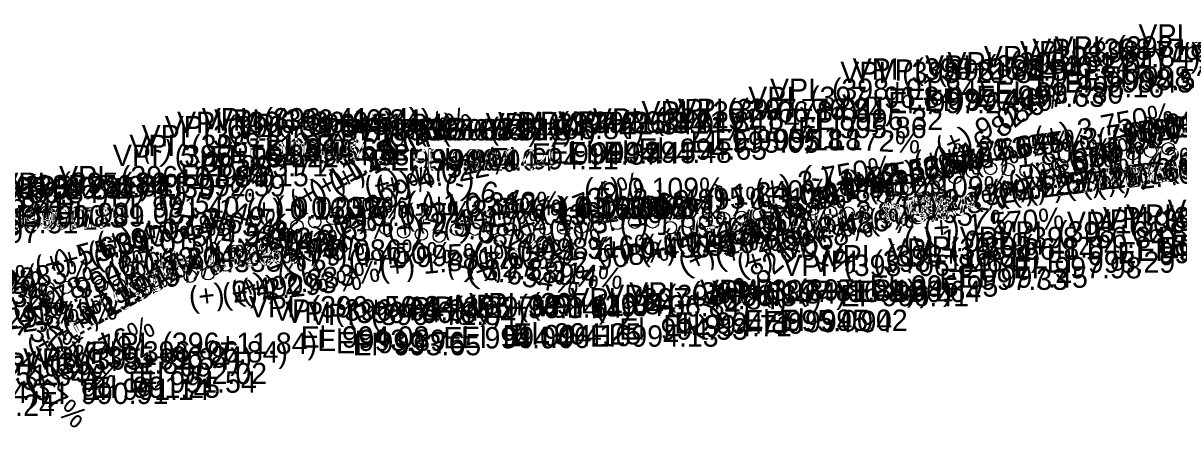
# Model space of a CAD drawing. Extents: x 16970812 to 16976737, y 12558429 to 12559451.
# Drawn here: x 16973947.7 to 16974272.7, y 12558853.6 to 12558967.5 of the extents above; entities that cross this region are included whole.
import ezdxf

# ---------------------------------------------------------------- set-up
doc = ezdxf.new("R2010")
doc.units = 0
doc.layers.add('RD_DDB_GradeTX', color=7, linetype='Continuous')
doc.layers.add('RD_DDB_PI', color=7, linetype='Continuous')

msp = doc.modelspace()

# ---------------------------------------------------------------- linework, layer by layer
at = {"layer": 'RD_DDB_PI'}
for centre in [(16974264.74, 12558931.47), (16974269.74, 12558932.13), (16974244.74, 12558928.33), (16974249.74, 12558929.2), (16974254.74, 12558930.1), (16974259.74, 12558930.78), (16974214.74, 12558925.66), (16974219.74, 12558926.59), (16974224.74, 12558926.3), (16974229.74, 12558925.95), (16974234.74, 12558926.55), (16974239.74, 12558927.44), (16974199.74, 12558921.35), (16974204.74, 12558922.52), (16974209.74, 12558924.04), (16974189.74, 12558918.63), (16974194.74, 12558920.9), (16974164.74, 12558915.19), (16974169.74, 12558915.22), (16974029.74, 12558911.58), (16974034.74, 12558912.59), (16974039.74, 12558912.25), (16974119.74, 12558911.49), (16974124.74, 12558911.57), (16974134.74, 12558911.69), (16974139.74, 12558911.94), (16974144.74, 12558912.55), (16974149.74, 12558912.88), (16974154.74, 12558913.61), (16974159.74, 12558914.54), (16974174.74, 12558914.3), (16974179.74, 12558914.03), (16974184.74, 12558914.42), (16974024.74, 12558910.39), (16974044.74, 12558910.98), (16974049.74, 12558909.7), (16974054.74, 12558908.78), (16974069.74, 12558909.49), (16974074.74, 12558909.53), (16974079.74, 12558909.53), (16974084.74, 12558909.51), (16974089.74, 12558909.49), (16974094.74, 12558909.6), (16974099.74, 12558909.86), (16974104.74, 12558910.11), (16974109.74, 12558910.58), (16974114.74, 12558911.18), (16974129.74, 12558909.97), (16974014.74, 12558905.08), (16974019.74, 12558907.85), (16974059.74, 12558908.14), (16974064.74, 12558907.56), (16974009.74, 12558902.26), (16974004.74, 12558899.44), (16973989.74, 12558895.58), (16973994.74, 12558896.3), (16973999.74, 12558897.02), (16973954.74, 12558892.88), (16973959.74, 12558893.18), (16973964.74, 12558893.48), (16973969.74, 12558893.76), (16973974.74, 12558893.85), (16973979.74, 12558894.47), (16973984.74, 12558895.01), (16973949.74, 12558891.86)]:
    msp.add_circle(centre, 1.75, dxfattribs=at)

# ---------------------------------------------------------------- texts
at = {"layer": 'RD_DDB_GradeTX'}
for s, rotation, p in [('(+) 16.821%', 40.0653, (16974205.12, 12558919.8)), ('(+) 9.086%', 24.4333, (16974206.01, 12558929.31)), ('(+) 3.526%', 9.9989, (16974257.4, 12558933.61)), ('(+) 3.508%', 9.9478, (16974262.53, 12558934.49)), ('(+) 2.766%', 7.8748, (16974269.24, 12558935.21)), ('(+) 11.072%', 28.9696, (16974030.11, 12558917.02)), ('(+) 10.173%', 26.9604, (16974035.47, 12558919.22)), ('(+) 3.750%', 10.6204, (16974232.74, 12558932.08)), ('(+) 3.015%', 8.5738, (16974250.25, 12558931.66)), ('(+) 2.996%', 8.5208, (16974254.14, 12558932.3)), ('(+) 2.942%', 8.3668, (16974258.77, 12558933.16)), ('(+) 2.854%', 8.1227, (16974263.74, 12558934.16)), ('(+) 11.289%', 29.4431, (16974024.86, 12558914.24)), ('(+) 2.795%', 7.9563, (16974234.02, 12558930.02)), ('(-) 1.172%', 356.6475, (16974162.39, 12558932.96)), ('(+) 2.753%', 7.8386, (16974198.59, 12558925.39)), ('(+) 2.665%', 7.5888, (16974203.8, 12558926.38)), ('(+) 2.645%', 7.5339, (16974208.8, 12558927.1)), ('(+) 6.068%', 16.8769, (16974225.76, 12558919.49)), ('(+) 6.467%', 17.9175, (16974231.2, 12558921.52)), ('(+) 3.576%', 10.1379, (16974270.02, 12558923.69)), ('(-) 5.082%', 345.742, (16973981.17, 12558930.23)), ('(+) 4.751%', 13.3624, (16974044.43, 12558918.15)), ('(+) 3.576%', 10.1379, (16974189.24, 12558921.43)), ('(+) 1.806%', 5.1588, (16974215.16, 12558925.75)), ('(-) 1.172%', 356.6475, (16974242.24, 12558928.28)), ('(-) 1.421%', 355.9359, (16974247.08, 12558927.72)), ('(+) 3.589%', 10.1734, (16974254.74, 12558920.99)), ('(+) 4.022%', 11.3718, (16974047.43, 12558918.2)), ('(+) 3.750%', 10.6204, (16974154.2, 12558917.36)), ('(+) 3.589%', 10.1734, (16974173.95, 12558918.69)), ('(+) 2.606%', 7.423, (16974178.19, 12558919.97)), ('(+) 3.526%', 9.9989, (16974178.7, 12558919.73)), ('(+) 4.694%', 13.2093, (16974220.75, 12558917.04)), ('(+) 2.776%', 7.9034, (16974241.07, 12558918.95)), ('(+) 2.889%', 8.2204, (16974245.59, 12558919.23)), ('(+) 2.408%', 6.8641, (16974249.56, 12558919.27)), ('(+) 11.299%', 29.4638, (16974025.86, 12558901.03)), ('(-) 6.401%', 342.2536, (16974065.93, 12558920.94)), ('(+) 6.914%', 19.069, (16974152.53, 12558908.32)), ('(-) 1.421%', 355.9359, (16974166.45, 12558921.42)), ('(+) 2.625%', 7.4787, (16974215, 12558915.88)), ('(+) 2.671%', 7.6059, (16974222.32, 12558916.71)), ('(+) 2.704%', 7.6996, (16974225.71, 12558917.06)), ('(+) 2.728%', 7.7659, (16974230.38, 12558917.62)), ('(-) 1.337%', 356.1754, (16973975.44, 12558919.56)), ('(+) 7.739%', 21.1528, (16974086.09, 12558906.17)), ('(+) 0.109%', 0.3115, (16974105.49, 12558917.87)), ('(-) 3.657%', 349.6382, (16974108.2, 12558917.32)), ('(+) 1.240%', 3.549, (16974135.05, 12558915.44)), ('(+) 6.467%', 17.9175, (16974151.63, 12558908.4)), ('(+) 0.998%', 2.857, (16974153.8, 12558915.65)), ('(+) 1.316%', 3.766, (16974166.62, 12558917)), ('(+) 0.109%', 0.3115, (16974185.49, 12558918.3)), ('(+) 2.732%', 7.779, (16974195.09, 12558912.87)), ('(-) 5.149%', 345.5629, (16973985.29, 12558916.99)), ('(-) 1.337%', 356.1754, (16974055.25, 12558914.22)), ('(+) 0.313%', 0.8955, (16974059.76, 12558913.55)), ('(+) 2.606%', 7.423, (16974098.9, 12558909.64)), ('(+) 0.995%', 2.8486, (16974118.68, 12558913.81)), ('(+) 0.313%', 0.8955, (16974139.75, 12558914.8)), ('(+) 2.408%', 6.8641, (16974170.17, 12558909.71)), ('(+) 3.716%', 10.5244, (16974176.8, 12558908.55)), ('(+) 3.508%', 9.9478, (16974185.88, 12558908.87)), ('(-) 3.657%', 349.6382, (16974188.97, 12558914.75)), ('(-) 3.654%', 349.6474, (16973988.02, 12558911.82)), ('(+) 0.160%', 0.4597, (16974010.49, 12558912.02)), ('(-) 0.023%', 359.9331, (16974013.21, 12558912.6)), ('(-) 0.055%', 359.8434, (16974018.51, 12558912.69)), ('(+) 9.676%', 25.818, (16974021.35, 12558897.47)), ('(+) 1.023%', 2.9289, (16974034.79, 12558909.54)), ('(+) 2.401%', 6.8459, (16974050.37, 12558906.47)), ('(+) 1.240%', 3.549, (16974055.21, 12558910.49)), ('(+) 2.436%', 6.945, (16974078.57, 12558907.51)), ('(+) 0.160%', 0.4597, (16974090.48, 12558912.66)), ('(-) 0.023%', 359.9331, (16974093.21, 12558912.51)), ('(+) 3.716%', 10.5244, (16974096.04, 12558905.76)), ('(-) 0.055%', 359.8434, (16974098.51, 12558912.47)), ('(-) 0.086%', 359.7535, (16974103.87, 12558912.43)), ('(+) 9.086%', 24.4333, (16974133.62, 12558896.43)), ('(+) 2.908%', 8.2731, (16974169.72, 12558906.69)), ('(+) 4.751%', 13.3624, (16973966.73, 12558899.7)), ('(+) 4.022%', 11.3718, (16973969.09, 12558902.44)), ('(-) 2.589%', 352.6251, (16973992.89, 12558907.71)), ('(+) 2.873%', 8.1736, (16974012.88, 12558901.94)), ('(-) 5.082%', 345.742, (16974058.55, 12558910.57)), ('(-) 5.149%', 345.5629, (16974065.6, 12558908.71)), ('(-) 1.097%', 356.8612, (16974115.41, 12558908.54)), ('(+) 2.401%', 6.8459, (16974131.2, 12558904.09)), ('(+) 1.806%', 5.1588, (16974136.58, 12558906.61)), ('(+) 4.694%', 13.2093, (16974143, 12558898.79)), ('(-) 6.401%', 342.2536, (16974145.55, 12558908.06)), ('(+) 2.436%', 6.945, (16974159.39, 12558905.27)), ('(+) 1.570%', 4.4896, (16974201.21, 12558906.69)), ('(+) 5.636%', 15.7391, (16973952.04, 12558895.75)), ('(+) 5.390%', 15.0828, (16973957.02, 12558896.93)), ('(+) 4.078%', 11.524, (16973968.16, 12558898.68)), ('(-) 2.314%', 353.401, (16973999.37, 12558906.06)), ('(+) 6.914%', 19.069, (16974073.28, 12558893.62)), ('(+) 1.881%', 5.372, (16974127.79, 12558903.24)), ('(+) 16.821%', 40.0653, (16974137.34, 12558878.48)), ('(+) 6.068%', 16.8769, (16974149.42, 12558896.33)), ('(-) 1.097%', 356.8612, (16974195.28, 12558904.16)), ('(+) 10.173%', 26.9604, (16973964.71, 12558883.22)), ('(+) 2.141%', 6.1104, (16974001.48, 12558899.81)), ('(+) 7.739%', 21.1528, (16974007.49, 12558888.62)), ('(-) 0.086%', 359.7535, (16974023.82, 12558900.77)), ('(+) 0.998%', 2.857, (16974074.5, 12558899.68)), ('(+) 1.316%', 3.766, (16974087.59, 12558899.77)), ('(+) 0.450%', 1.2892, (16974108.94, 12558900.92)), ('(+) 1.023%', 2.9289, (16974115.29, 12558901.64)), ('(+) 1.570%', 4.4896, (16974121.47, 12558900.43)), ('(+) 8.543%', 23.129, (16973950.47, 12558884.69)), ('(+) 11.072%', 28.9696, (16973960.75, 12558878.62)), ('(+) 1.204%', 3.4464, (16973975.06, 12558897.11)), ('(+) 1.192%', 3.4094, (16973981.71, 12558897.5)), ('(+) 1.123%', 3.2124, (16973986.31, 12558897.7)), ('(+) 0.338%', 0.9695, (16973988.09, 12558897.07)), ('(+) 0.450%', 1.2892, (16974028.96, 12558899.12)), ('(+) 0.995%', 2.8486, (16974039.38, 12558897.84)), ('(+) 1.881%', 5.372, (16974048.16, 12558895.75)), ('(-) 2.589%', 352.6251, (16974072.19, 12558897.45)), ('(+) 2.908%', 8.2731, (16974090.6, 12558895.19)), ('(-) 1.481%', 355.7651, (16973912.32, 12558894.42)), ('(+) 2.883%', 8.2022, (16973928.46, 12558889.78)), ('(+) 7.990%', 21.7763, (16973946.21, 12558882.51)), ('(+) 11.289%', 29.4431, (16973955.84, 12558875.28)), ('(+) 5.397%', 15.102, (16973965.43, 12558886.77)), ('(+) 2.883%', 8.2022, (16974009.3, 12558889.3)), ('(-) 3.654%', 349.6474, (16974066.64, 12558897.46)), ('(-) 2.314%', 353.401, (16974078.81, 12558896.87)), ('(+) 2.490%', 7.0961, (16973913.87, 12558889.29)), ('(-) 1.721%', 355.0806, (16973917.28, 12558893.79)), ('(-) 2.923%', 351.6863, (16973918.33, 12558892.6)), ('(-) 3.336%', 350.53, (16973923.21, 12558891.51)), ('(+) 11.299%', 29.4638, (16973950.95, 12558872.49)), ('(+) 2.490%', 7.0961, (16973994.7, 12558887.26)), ('(+) 2.293%', 6.5394, (16974003.99, 12558888.15)), ('(-) 7.737%', 338.8521, (16973929.09, 12558886.45)), ('(+) 2.141%', 6.1104, (16973923.24, 12558879.37)), ('(+) 2.293%', 6.5394, (16973924.55, 12558879.05)), ('(+) 2.873%', 8.1736, (16973935.45, 12558878.69)), ('(+) 9.676%', 25.818, (16973949.83, 12558862.87)), ('(-) 16.557%', 320.3797, (16973930.29, 12558879.81)), ('(-) 4.089%', 348.4452, (16973936.78, 12558871.98))]:
    msp.add_text(s, height=6, rotation=rotation, dxfattribs=at).set_placement(p)
at = {"layer": 'RD_DDB_PI'}
for s, p in [('VPI  (399+06.84)', (16974261.33, 12558961.18)), ('VPI  (398+71.84)', (16974228.04, 12558956.47)), ('VPI  (398+76.84)', (16974231.5, 12558957.13)), ('VPI  (398+81.84)', (16974237.74, 12558957.8)), ('VPI  (398+46.84)', (16974201.33, 12558952.44)), ('VPI  (398+51.84)', (16974207.63, 12558953.33)), ('VPI  (398+61.84)', (16974217.86, 12558955.1)), ('VPI  (398+21.84)', (16974177.51, 12558950.66)), ('VPI  (398+26.84)', (16974180.97, 12558951.59)), ('VPI  (398+31.84)', (16974187.45, 12558951.3)), ('El  998.70', (16974250.94, 12558949.3)), ('VPI  (398+01.84)', (16974157.74, 12558945.9)), ('El  998.16', (16974232.42, 12558946.6)), ('El  998.43', (16974240.5, 12558947.97)), ('El  998.56', (16974245.65, 12558948.63)), ('VPI  (397+96.84)', (16974151.62, 12558943.63)), ('El  997.46', (16974196.18, 12558943.09)), ('El  997.40', (16974201.06, 12558942.8)), ('El  997.63', (16974215.79, 12558943.94)), ('El  997.80', (16974220.94, 12558944.83)), ('VPI  (397+66.84)', (16974121.62, 12558939.54)), ('VPI  (397+71.84)', (16974128.33, 12558940.19)), ('VPI  (397+76.84)', (16974131.8, 12558940.22)), ('El  997.27', (16974191, 12558942.16)), ('VPI  (396+36.84)', (16973991.03, 12558936.58)), ('VPI  (396+41.84)', (16973997.98, 12558937.59)), ('VPI  (396+46.84)', (16974001.44, 12558937.25)), ('VPI  (397+21.84)', (16974077.8, 12558936.18)), ('VPI  (397+26.84)', (16974081.27, 12558936.49)), ('VPI  (397+31.84)', (16974087.74, 12558936.57)), ('VPI  (397+41.84)', (16974098.16, 12558936.69)), ('VPI  (397+51.84)', (16974107.92, 12558937.55)), ('El  996.32', (16974170.26, 12558937.4)), ('VPI  (396+31.84)', (16973987.57, 12558935.39)), ('VPI  (396+51.84)', (16974007.74, 12558935.98)), ('VPI  (396+76.84)', (16974031.62, 12558934.49)), ('VPI  (396+81.84)', (16974037.86, 12558934.53)), ('VPI  (396+86.84)', (16974041.33, 12558934.53)), ('VPI  (396+91.84)', (16974047.98, 12558934.51)), ('VPI  (397+06.84)', (16974061.5, 12558934.86)), ('El  995.86', (16974165.65, 12558935.13)), ('VPI  (396+21.84)', (16973977.63, 12558930.08)), ('VPI  (396+26.84)', (16973981.09, 12558932.85)), ('El  995.05', (16974135.44, 12558931.04)), ('El  995.18', (16974142.21, 12558931.69)), ('El  995.18', (16974147.21, 12558931.72)), ('VPI  (396+16.84)', (16973972.98, 12558927.26)), ('El  994.22', (16974000.32, 12558926.89)), ('El  994.45', (16974005.79, 12558928.08)), ('El  994.66', (16974011, 12558929.09)), ('El  994.59', (16974015.76, 12558928.75)), ('El  994.33', (16974020.2, 12558927.48)), ('El  994.37', (16974090.76, 12558927.68)), ('El  994.44', (16974096, 12558927.99)), ('El  994.45', (16974100.79, 12558928.07)), ('El  994.48', (16974110.91, 12558928.19)), ('El  994.65', (16974120.79, 12558929.05)), ('El  993.71', (16973997.3, 12558924.35)), ('El  994.04', (16974045.88, 12558925.99)), ('El  994.04', (16974050.88, 12558926.03)), ('El  994.04', (16974055.88, 12558926.03)), ('El  994.04', (16974060.88, 12558926.01)), ('El  994.11', (16974079.07, 12558926.36)), ('VPI  (396+01.84)', (16973957.86, 12558921.3)), ('El  993.15', (16973991.92, 12558921.58)), ('VPI  (395+56.84)', (16973910.97, 12558916.86)), ('VPI  (395+61.84)', (16973917.74, 12558917.88)), ('VPI  (395+66.84)', (16973921.21, 12558918.18)), ('VPI  (395+71.84)', (16973927.92, 12558918.48)), ('VPI  (395+76.84)', (16973931.39, 12558918.76)), ('VPI  (395+86.84)', (16973941.09, 12558919.47)), ('El  992.59', (16973985.41, 12558918.76)), ('VPI  (395+46.84)', (16973901.21, 12558914.17)), ('VPI  (395+41.84)', (16973897.74, 12558912.76)), ('El  990.89', (16973945.76, 12558910.26)), ('El  991.03', (16973957.03, 12558910.97)), ('El  991.40', (16973972.42, 12558912.8)), ('VPI  (399+01.84)', (16974257.86, 12558910.48)), ('VPI  (399+11.84)', (16974269.51, 12558911.87)), ('El  990.51', (16973927.18, 12558908.36)), ('El  990.71', (16973932.6, 12558909.38)), ('El  990.77', (16973936.24, 12558909.68)), ('El  990.83', (16973940.38, 12558909.98)), ('VPI  (398+86.84)', (16974241.21, 12558908.45)), ('VPI  (398+91.84)', (16974247.86, 12558909.12)), ('VPI  (398+96.84)', (16974251.33, 12558909.8)), ('El  989.97', (16973916.06, 12558905.67)), ('VPI  (398+56.84)', (16974211.09, 12558904.2)), ('VPI  (398+66.84)', (16974221.33, 12558905.78)), ('VPI  (398+36.84)', (16974190.91, 12558900.95)), ('VPI  (398+41.84)', (16974197.86, 12558901.55)), ('El  998.96', (16974260.88, 12558900.62)), ('El  999.10', (16974267.42, 12558901.3)), ('El  999.23', (16974270.26, 12558901.98)), ('VPI  (398+11.84)', (16974169.4, 12558897.52)), ('VPI  (398+16.84)', (16974172.86, 12558899.04)), ('El  998.29', (16974235.53, 12558897.28)), ('El  998.83', (16974255.38, 12558899.95)), ('VPI  (398+06.84)', (16974161.21, 12558896.35)), ('El  997.98', (16974226.09, 12558895.7)), ('El  997.33', (16974205.38, 12558892.45)), ('El  997.45', (16974210.97, 12558893.05)), ('VPI  (397+56.84)', (16974111.39, 12558887.88)), ('VPI  (397+61.84)', (16974118.16, 12558888.61)), ('VPI  (397+81.84)', (16974138.04, 12558889.3)), ('VPI  (397+86.84)', (16974141.5, 12558889.03)), ('VPI  (397+91.84)', (16974148.16, 12558889.42)), ('El  996.41', (16974177.54, 12558887.85)), ('El  996.64', (16974181, 12558889.02)), ('El  996.95', (16974185.79, 12558890.54)), ('VPI  (396+56.84)', (16974011.21, 12558884.7)), ('VPI  (396+96.84)', (16974051.44, 12558884.49)), ('VPI  (397+01.84)', (16974058.04, 12558884.6)), ('VPI  (397+11.84)', (16974069.69, 12558885.11)), ('VPI  (397+16.84)', (16974073.16, 12558885.58)), ('VPI  (397+36.84)', (16974091.21, 12558884.97)), ('VPI  (397+46.84)', (16974101.62, 12558886.94)), ('VPI  (396+61.84)', (16974017.98, 12558883.78)), ('VPI  (396+66.84)', (16974021.44, 12558883.14)), ('VPI  (396+71.84)', (16974028.16, 12558882.56)), ('El  995.02', (16974160.32, 12558880.92)), ('El  994.53', (16974115.38, 12558878.44)), ('El  994.71', (16974127.71, 12558879.38)), ('El  994.86', (16974130.88, 12558880.11)), ('El  995.00', (16974150.53, 12558880.8)), ('El  994.94', (16974156, 12558880.53)), ('VPI  (396+11.84)', (16973969.51, 12558874.44)), ('El  994.08', (16974025.79, 12558876.2)), ('El  993.89', (16974030.47, 12558875.28)), ('El  993.76', (16974035.76, 12558874.64)), ('El  994.04', (16974065.88, 12558875.99)), ('El  994.06', (16974070.88, 12558876.1)), ('El  994.16', (16974082.54, 12558876.61)), ('El  994.25', (16974085.44, 12558877.08)), ('El  994.13', (16974107.15, 12558876.47)), ('VPI  (396+06.84)', (16973961.33, 12558872.02)), ('El  993.65', (16974040.38, 12558874.06)), ('VPI  (395+81.84)', (16973937.63, 12558868.85)), ('VPI  (395+91.84)', (16973947.74, 12558870.01)), ('VPI  (395+96.84)', (16973951.21, 12558870.58)), ('VPI  (395+51.84)', (16973907.51, 12558865.51)), ('El  992.02', (16973980.2, 12558865.94)), ('El  991.14', (16973964.07, 12558861.51)), ('El  991.25', (16973966.98, 12558862.08)), ('El  991.54', (16973977.3, 12558863.52)), ('VPI  (395+36.84)', (16973890.79, 12558860.62)), ('El  990.91', (16973952.42, 12558860.35)), ('El  990.24', (16973920.53, 12558857.01))]:
    msp.add_text(s, height=6, dxfattribs=at).set_placement(p)

doc.saveas('drawing.dxf')
